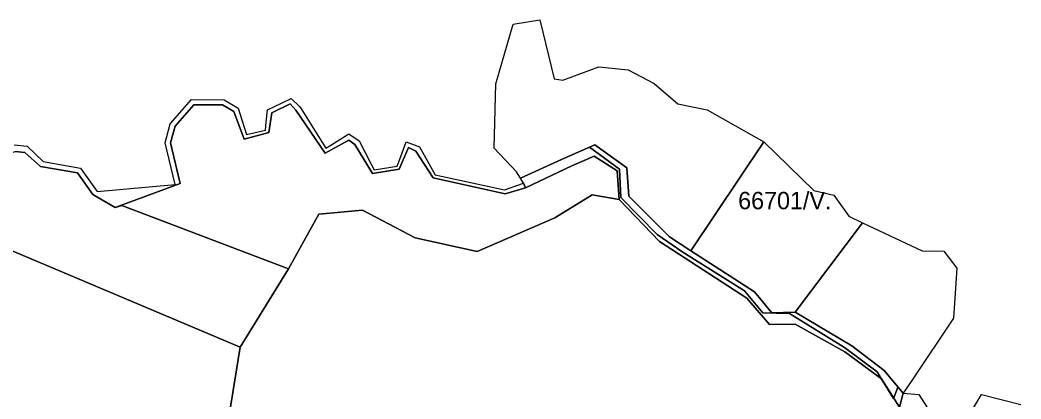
# Model space of a CAD drawing. Extents: x -522079 to -518833, y -1142400 to -1139961.
# Drawn here: x -519448.3 to -519161.2, y -1141371.1 to -1141262.2 of the extents above; entities that cross this region are included whole.
import ezdxf

# ---------------------------------------------------------------- set-up
doc = ezdxf.new("R2010")
doc.units = 0
for name, color, linetype in [('95610013', 7, 'Continuous'), ('95620013', 7, 'Continuous'), ('95630013', 7, 'Continuous'), ('95660013', 7, 'Continuous')]:
    doc.layers.add(name, color=color, linetype=linetype)

msp = doc.modelspace()

# ---------------------------------------------------------------- linework, layer by layer
at = {"layer": '95610013'}
for points in [[(-519311.83, -1141280.54), (-519306.82, -1141263.47), (-519299.19, -1141262.23), (-519295.1, -1141279.15), (-519292.59, -1141279.53), (-519282.24, -1141275.71), (-519273.89, -1141276.5), (-519266.36, -1141280.43), (-519259.58, -1141286.33), (-519251.16, -1141288.07), (-519234.97, -1141297.23), (-519255.87, -1141328.5), (-519261.98, -1141324.54), (-519273.62, -1141312.83), (-519274.28, -1141304.73), (-519283.38, -1141298.07), (-519292.93, -1141302.27), (-519304.74, -1141307.68), (-519305.93, -1141305.82), (-519312.28, -1141299.01)], [(-519206.65, -1141320.44), (-519225.91, -1141346.11), (-519232.62, -1141346.31), (-519237.64, -1141340.3), (-519255.87, -1141328.5), (-519234.97, -1141297.23), (-519220.59, -1141311.22), (-519214.82, -1141312.52), (-519210.53, -1141318.6)], [(-519206.65, -1141320.44), (-519189.49, -1141328.56), (-519183.26, -1141328.59), (-519179.55, -1141333.52), (-519180.48, -1141347.87), (-519192.3, -1141365.49), (-519194.96, -1141369.43), (-519200.4, -1141362.91), (-519209.66, -1141355.81), (-519225.91, -1141346.11)]]:
    msp.add_lwpolyline(points, close=True, dxfattribs=at)
at = {"layer": '95620013'}
for points in [[(-519419.15, -1141315.48), (-519420.99, -1141316.12), (-519402.36, -1141309.19), (-519405.13, -1141297.52), (-519403.84, -1141292.74), (-519398.45, -1141286.57), (-519390.2, -1141286.63), (-519386.96, -1141288.54), (-519383.98, -1141296.49), (-519376.93, -1141294.5), (-519376.04, -1141288.86), (-519370.85, -1141286.3), (-519369.21, -1141288.13), (-519360.8, -1141300.45), (-519354, -1141296.72), (-519352.22, -1141297.98), (-519347.17, -1141306.35), (-519339.54, -1141305.07), (-519336.85, -1141298.85), (-519334.73, -1141299.89), (-519329.81, -1141307.56), (-519309.12, -1141312.18), (-519303.35, -1141310.46), (-519290.01, -1141304.08), (-519283.62, -1141301.34), (-519277.01, -1141305.57), (-519276.42, -1141313.78), (-519284.21, -1141312.41), (-519294.89, -1141319.05), (-519317.19, -1141328.69), (-519334.98, -1141324.76), (-519350.02, -1141316.82), (-519362.63, -1141317.99), (-519371.28, -1141333.68)], [(-519385.2, -1141356.16), (-519465.42, -1141322.27), (-519465.26, -1141311.18), (-519465.25, -1141309.34), (-519466.74, -1141308.54), (-519468.94, -1141304.33), (-519461.31, -1141303.85), (-519449.71, -1141299.98), (-519446.9, -1141300.29), (-519442.41, -1141304.27), (-519431.85, -1141306.14), (-519427.38, -1141312.36), (-519420.99, -1141316.12), (-519419.15, -1141315.48), (-519371.28, -1141333.68)], [(-519494.92, -1141380.6), (-519493.9, -1141370.24), (-519484.66, -1141353.81), (-519477.91, -1141348.96), (-519470.8, -1141337.38), (-519465.42, -1141322.27), (-519385.2, -1141356.16), (-519392.16, -1141399.31), (-519386.73, -1141417.35), (-519402.53, -1141416.1), (-519450.75, -1141420.94), (-519466.91, -1141416.21), (-519490.7, -1141404.57), (-519496.45, -1141402.69), (-519489.99, -1141393.96), (-519488.36, -1141388.76)]]:
    msp.add_lwpolyline(points, close=True, dxfattribs=at)
msp.add_lwpolyline([(-519392.16, -1141399.31), (-519385.2, -1141356.16), (-519371.28, -1141333.68), (-519362.63, -1141317.99), (-519350.02, -1141316.82), (-519334.98, -1141324.76), (-519317.19, -1141328.69), (-519294.89, -1141319.05), (-519284.21, -1141312.41), (-519276.42, -1141313.78), (-519264.89, -1141325.79), (-519239.84, -1141342.13), (-519233.32, -1141349.64), (-519225.95, -1141349.55), (-519211.68, -1141357.48), (-519201.22, -1141365.24), (-519195.98, -1141373.38)], dxfattribs=at)
at = {"layer": '95630013'}
for points in [[(-519449.98, -1141298.09), (-519446.22, -1141298.48), (-519441.7, -1141302.87), (-519430.99, -1141304.77), (-519426.16, -1141311.48), (-519403.83, -1141309.49), (-519406.68, -1141297.5), (-519405.2, -1141292.02), (-519399.13, -1141285.07), (-519389.78, -1141285.13), (-519385.69, -1141287.55), (-519385.12, -1141289.38), (-519383.31, -1141295.11), (-519377.88, -1141293.85), (-519377.66, -1141291.53), (-519377.33, -1141288.06), (-519373.33, -1141286.11), (-519370.55, -1141284.76), (-519368.04, -1141287.17), (-519367.51, -1141288.01), (-519361.74, -1141297.24), (-519360.6, -1141299.07), (-519359.18, -1141298.18), (-519353.95, -1141294.93), (-519351.06, -1141296.96), (-519347.55, -1141303.63), (-519346.7, -1141305.23), (-519340.12, -1141304.19), (-519339.07, -1141301.4), (-519337.51, -1141297.26), (-519333.7, -1141298.67), (-519329.18, -1141306.68), (-519309.3, -1141311.02), (-519303.86, -1141309.05), (-519303.35, -1141310.46), (-519309.12, -1141312.18), (-519329.81, -1141307.56), (-519334.73, -1141299.89), (-519336.85, -1141298.85), (-519339.54, -1141305.07), (-519347.17, -1141306.35), (-519352.22, -1141297.98), (-519354, -1141296.72), (-519360.8, -1141300.45), (-519369.21, -1141288.13), (-519370.85, -1141286.3), (-519376.04, -1141288.86), (-519376.93, -1141294.5), (-519383.98, -1141296.49), (-519386.96, -1141288.54), (-519390.2, -1141286.63), (-519398.45, -1141286.57), (-519403.84, -1141292.74), (-519405.13, -1141297.52), (-519402.36, -1141309.19), (-519420.99, -1141316.12), (-519427.38, -1141312.36), (-519431.85, -1141306.14), (-519442.41, -1141304.27), (-519446.9, -1141300.29), (-519449.71, -1141299.98)], [(-519195.98, -1141373.38), (-519194.96, -1141369.43), (-519190.42, -1141369.81), (-519187.2, -1141374.82)], [(-519180.54, -1141383.29), (-519172.49, -1141369.75), (-519161.16, -1141372.68)]]:
    msp.add_lwpolyline(points, dxfattribs=at)
msp.add_lwpolyline([(-519225.91, -1141346.11), (-519209.66, -1141355.81), (-519200.4, -1141362.91), (-519194.96, -1141369.43), (-519195.98, -1141373.38), (-519201.22, -1141365.24), (-519211.68, -1141357.48), (-519225.95, -1141349.55), (-519233.32, -1141349.64), (-519239.84, -1141342.13), (-519264.89, -1141325.79), (-519276.42, -1141313.78), (-519277.01, -1141305.57), (-519283.62, -1141301.34), (-519290.01, -1141304.08), (-519303.35, -1141310.46), (-519303.86, -1141309.05), (-519304.74, -1141307.68), (-519292.93, -1141302.27), (-519283.38, -1141298.07), (-519274.28, -1141304.73), (-519273.62, -1141312.83), (-519261.98, -1141324.54), (-519255.87, -1141328.5), (-519237.64, -1141340.3), (-519232.62, -1141346.31)], close=True, dxfattribs=at)
at = {"layer": '95660013'}
msp.add_lwpolyline([(-519305.93, -1141305.82), (-519312.28, -1141299.01), (-519311.83, -1141280.54), (-519306.82, -1141263.47), (-519299.19, -1141262.23), (-519295.1, -1141279.15), (-519292.59, -1141279.53), (-519282.24, -1141275.71), (-519273.89, -1141276.5), (-519266.36, -1141280.43), (-519259.58, -1141286.33), (-519251.16, -1141288.07), (-519234.97, -1141297.23), (-519220.59, -1141311.22), (-519214.82, -1141312.52), (-519210.53, -1141318.6), (-519206.65, -1141320.44), (-519189.49, -1141328.56), (-519183.26, -1141328.59), (-519179.55, -1141333.52), (-519180.48, -1141347.87), (-519192.3, -1141365.49), (-519194.96, -1141369.43), (-519196.47, -1141367.62), (-519197.68, -1141370.73), (-519197.76, -1141370.93), (-519201.3, -1141365.18), (-519202.46, -1141363.29), (-519211.75, -1141356.23), (-519227.56, -1141346.51), (-519235.22, -1141346.32), (-519240.47, -1141339.97), (-519258.15, -1141328.91), (-519265.54, -1141323.87), (-519275.96, -1141313.17), (-519276.3, -1141305.09), (-519284.95, -1141298.76), (-519292.93, -1141302.27), (-519304.74, -1141307.68)], close=True, dxfattribs=at)
for points in [[(-519449.98, -1141298.09), (-519446.22, -1141298.48), (-519441.7, -1141302.87), (-519430.99, -1141304.77), (-519426.16, -1141311.48), (-519403.83, -1141309.49), (-519406.68, -1141297.5), (-519405.2, -1141292.02), (-519399.13, -1141285.07), (-519389.78, -1141285.13), (-519385.69, -1141287.55), (-519385.12, -1141289.38), (-519383.31, -1141295.11), (-519377.88, -1141293.85), (-519377.66, -1141291.53), (-519377.33, -1141288.06), (-519373.33, -1141286.11), (-519370.55, -1141284.76), (-519368.04, -1141287.17), (-519367.51, -1141288.01), (-519361.74, -1141297.24), (-519360.6, -1141299.07), (-519359.18, -1141298.18), (-519353.95, -1141294.93), (-519351.06, -1141296.96), (-519347.55, -1141303.63), (-519346.7, -1141305.23), (-519340.12, -1141304.19), (-519339.07, -1141301.4), (-519337.51, -1141297.26), (-519333.7, -1141298.67), (-519329.18, -1141306.68), (-519309.3, -1141311.02), (-519303.86, -1141309.05), (-519304.74, -1141307.68), (-519292.93, -1141302.27), (-519284.95, -1141298.76), (-519276.3, -1141305.09), (-519275.96, -1141313.17), (-519265.54, -1141323.87), (-519258.15, -1141328.91), (-519240.47, -1141339.97), (-519235.22, -1141346.32), (-519227.56, -1141346.51), (-519211.75, -1141356.23), (-519202.46, -1141363.29), (-519201.3, -1141365.18), (-519197.76, -1141370.93), (-519197.68, -1141370.73), (-519196.47, -1141367.62), (-519194.96, -1141369.43), (-519190.42, -1141369.81), (-519187.2, -1141374.82)], [(-519180.54, -1141383.29), (-519172.49, -1141369.75), (-519161.16, -1141372.68)]]:
    msp.add_lwpolyline(points, dxfattribs=at)

# ---------------------------------------------------------------- texts
msp.add_text('66701/V.', height=5, rotation=0, dxfattribs=at).set_placement((-519242.3, -1141316.58))

doc.saveas('drawing.dxf')
